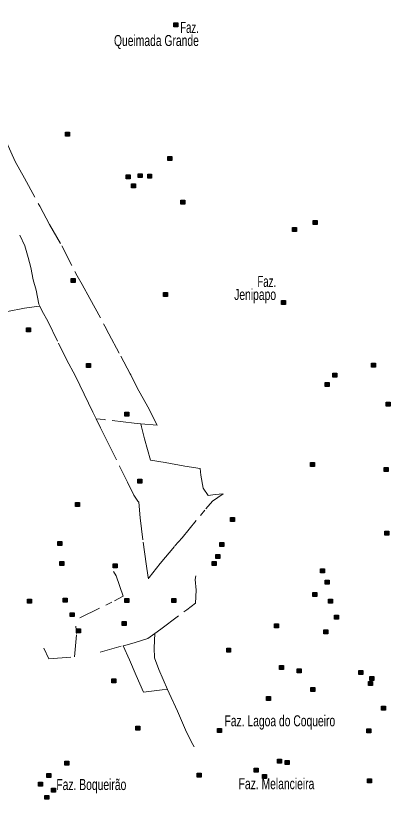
# Model space of a CAD drawing. Extents: x 445.6 to 500, y 8618.1 to 8673.4.
# Drawn here: x 452.48 to 457.92, y 8644.3 to 8655.7 of the extents above; entities that cross this region are included whole.
import ezdxf
from ezdxf.enums import TextEntityAlignment as Align

# ---------------------------------------------------------------- set-up
doc = ezdxf.new("R2010")
doc.units = 0
doc.header["$LTSCALE"] = 0.064
doc.linetypes.add('DOT_DASHED', pattern=[7.7, 5, -1.2, 0.3, -1.2])
doc.layers.add('2', color=7, linetype='Continuous', lineweight=25)
doc.layers.add('22', color=7, linetype='DOT_DASHED', lineweight=13)
doc.layers.add('61', color=7, linetype='Continuous')

msp = doc.modelspace()

# ---------------------------------------------------------------- hatches: boundary and pattern name
at = {"layer": '2'}
for points in [[(454.7723, 8655.5913), (454.8303, 8655.5913), (454.8303, 8655.5333), (454.7723, 8655.5333)], [(453.2027, 8654.0044), (453.2607, 8654.0044), (453.2607, 8653.9464), (453.2027, 8653.9464)], [(454.688, 8653.6496), (454.746, 8653.6496), (454.746, 8653.5916), (454.688, 8653.5916)], [(454.08, 8653.3819), (454.138, 8653.3819), (454.138, 8653.3239), (454.08, 8653.3239)], [(454.2557, 8653.3988), (454.3137, 8653.3988), (454.3137, 8653.3408), (454.2557, 8653.3408)], [(454.3941, 8653.3921), (454.4521, 8653.3921), (454.4521, 8653.3341), (454.3941, 8653.3341)], [(454.1577, 8653.2532), (454.2157, 8653.2532), (454.2157, 8653.1952), (454.1577, 8653.1952)], [(454.8772, 8653.0126), (454.9352, 8653.0126), (454.9352, 8652.9546), (454.8772, 8652.9546)], [(456.7994, 8652.718), (456.8574, 8652.718), (456.8574, 8652.66), (456.7994, 8652.66)], [(456.4988, 8652.6164), (456.5568, 8652.6164), (456.5568, 8652.5584), (456.4988, 8652.5584)], [(453.2852, 8651.8742), (453.3432, 8651.8742), (453.3432, 8651.8162), (453.2852, 8651.8162)], [(454.6219, 8651.671), (454.6799, 8651.671), (454.6799, 8651.613), (454.6219, 8651.613)], [(456.338, 8651.5524), (456.396, 8651.5524), (456.396, 8651.4944), (456.338, 8651.4944)], [(452.634, 8651.1585), (452.692, 8651.1585), (452.692, 8651.1005), (452.634, 8651.1005)], [(453.5082, 8650.6375), (453.5662, 8650.6375), (453.5662, 8650.5795), (453.5082, 8650.5795)], [(457.6418, 8650.6444), (457.6998, 8650.6444), (457.6998, 8650.5864), (457.6418, 8650.5864)], [(457.0816, 8650.4982), (457.1396, 8650.4982), (457.1396, 8650.4402), (457.0816, 8650.4402)], [(456.9696, 8650.3598), (457.0276, 8650.3598), (457.0276, 8650.3018), (456.9696, 8650.3018)], [(457.859, 8650.0749), (457.917, 8650.0749), (457.917, 8650.0169), (457.859, 8650.0169)], [(454.0636, 8649.9323), (454.1216, 8649.9323), (454.1216, 8649.8743), (454.0636, 8649.8743)], [(456.7603, 8649.1973), (456.8183, 8649.1973), (456.8183, 8649.1393), (456.7603, 8649.1393)], [(457.8286, 8649.1263), (457.8866, 8649.1263), (457.8866, 8649.0683), (457.8286, 8649.0683)], [(454.2494, 8648.9565), (454.3074, 8648.9565), (454.3074, 8648.8985), (454.2494, 8648.8985)], [(453.3441, 8648.6177), (453.4021, 8648.6177), (453.4021, 8648.5597), (453.3441, 8648.5597)], [(455.595, 8648.4011), (455.653, 8648.4011), (455.653, 8648.3431), (455.595, 8648.3431)], [(457.8387, 8648.2008), (457.8967, 8648.2008), (457.8967, 8648.1428), (457.8387, 8648.1428)], [(453.0908, 8648.0485), (453.1488, 8648.0485), (453.1488, 8647.9905), (453.0908, 8647.9905)], [(455.4431, 8648.035), (455.5011, 8648.035), (455.5011, 8647.977), (455.4431, 8647.977)], [(455.3823, 8647.8588), (455.4403, 8647.8588), (455.4403, 8647.8008), (455.3823, 8647.8008)], [(453.1172, 8647.7571), (453.1752, 8647.7571), (453.1752, 8647.6991), (453.1172, 8647.6991)], [(455.3317, 8647.7571), (455.3897, 8647.7571), (455.3897, 8647.6991), (455.3317, 8647.6991)], [(453.8947, 8647.7233), (453.9527, 8647.7233), (453.9527, 8647.6653), (453.8947, 8647.6653)], [(456.9017, 8647.6521), (456.9597, 8647.6521), (456.9597, 8647.5941), (456.9017, 8647.5941)], [(456.9726, 8647.4895), (457.0306, 8647.4895), (457.0306, 8647.4315), (456.9726, 8647.4315)], [(456.7902, 8647.3066), (456.8482, 8647.3066), (456.8482, 8647.2486), (456.7902, 8647.2486)], [(452.6494, 8647.2117), (452.7074, 8647.2117), (452.7074, 8647.1537), (452.6494, 8647.1537)], [(453.1662, 8647.2253), (453.2242, 8647.2253), (453.2242, 8647.1673), (453.1662, 8647.1673)], [(454.0602, 8647.2219), (454.1182, 8647.2219), (454.1182, 8647.1639), (454.0602, 8647.1639)], [(454.7459, 8647.2219), (454.8039, 8647.2219), (454.8039, 8647.1639), (454.7459, 8647.1639)], [(457.0179, 8647.2113), (457.0759, 8647.2113), (457.0759, 8647.1533), (457.0179, 8647.1533)], [(453.2709, 8647.0152), (453.3289, 8647.0152), (453.3289, 8646.9572), (453.2709, 8646.9572)], [(457.1091, 8646.9775), (457.1671, 8646.9775), (457.1671, 8646.9195), (457.1091, 8646.9195)], [(454.0218, 8646.8886), (454.0798, 8646.8886), (454.0798, 8646.8306), (454.0218, 8646.8306)], [(456.2369, 8646.8525), (456.2949, 8646.8525), (456.2949, 8646.7945), (456.2369, 8646.7945)], [(453.3621, 8646.7781), (453.4201, 8646.7781), (453.4201, 8646.7201), (453.3621, 8646.7201)], [(456.9523, 8646.7645), (457.0103, 8646.7645), (457.0103, 8646.7065), (456.9523, 8646.7065)], [(455.5411, 8646.4968), (455.5991, 8646.4968), (455.5991, 8646.4388), (455.5411, 8646.4388)], [(456.3065, 8646.2456), (456.3645, 8646.2456), (456.3645, 8646.1876), (456.3065, 8646.1876)], [(456.5666, 8646.1982), (456.6246, 8646.1982), (456.6246, 8646.1402), (456.5666, 8646.1402)], [(457.4604, 8646.1722), (457.5184, 8646.1722), (457.5184, 8646.1142), (457.4604, 8646.1142)], [(453.8726, 8646.0522), (453.9306, 8646.0522), (453.9306, 8645.9942), (453.8726, 8645.9942)], [(457.6192, 8646.0875), (457.6772, 8646.0875), (457.6772, 8646.0295), (457.6192, 8646.0295)], [(456.7625, 8645.9271), (456.8205, 8645.9271), (456.8205, 8645.8691), (456.7625, 8645.8691)], [(457.6023, 8646.013), (457.6603, 8646.013), (457.6603, 8645.955), (457.6023, 8645.955)], [(456.1173, 8645.7984), (456.1753, 8645.7984), (456.1753, 8645.7404), (456.1173, 8645.7404)], [(457.7903, 8645.6563), (457.8483, 8645.6563), (457.8483, 8645.5983), (457.7903, 8645.5983)], [(454.2234, 8645.3658), (454.2814, 8645.3658), (454.2814, 8645.3078), (454.2234, 8645.3078)], [(455.408, 8645.3308), (455.466, 8645.3308), (455.466, 8645.2728), (455.408, 8645.2728)], [(457.5775, 8645.3243), (457.6355, 8645.3243), (457.6355, 8645.2663), (457.5775, 8645.2663)], [(453.1921, 8644.8536), (453.2501, 8644.8536), (453.2501, 8644.7956), (453.1921, 8644.7956)], [(456.2795, 8644.8836), (456.3375, 8644.8836), (456.3375, 8644.8256), (456.2795, 8644.8256)], [(456.391, 8644.8633), (456.449, 8644.8633), (456.449, 8644.8053), (456.391, 8644.8053)], [(452.9294, 8644.677), (452.9874, 8644.677), (452.9874, 8644.619), (452.9294, 8644.619)], [(455.1108, 8644.6803), (455.1688, 8644.6803), (455.1688, 8644.6223), (455.1108, 8644.6223)], [(455.9422, 8644.755), (456.0002, 8644.755), (456.0002, 8644.697), (455.9422, 8644.697)], [(456.0599, 8644.66), (456.1179, 8644.66), (456.1179, 8644.602), (456.0599, 8644.602)], [(457.5876, 8644.5992), (457.6456, 8644.5992), (457.6456, 8644.5412), (457.5876, 8644.5412)], [(452.807, 8644.5487), (452.865, 8644.5487), (452.865, 8644.4907), (452.807, 8644.4907)], [(452.9962, 8644.464), (453.0542, 8644.464), (453.0542, 8644.406), (452.9962, 8644.406)], [(452.9016, 8644.359), (452.9596, 8644.359), (452.9596, 8644.301), (452.9016, 8644.301)]]:
    msp.add_hatch(color=256, dxfattribs=at).paths.add_polyline_path(points)

# ---------------------------------------------------------------- linework, layer by layer
for points in [[(454.7723, 8655.5913), (454.8303, 8655.5913), (454.8303, 8655.5333), (454.7723, 8655.5333)], [(453.2027, 8654.0044), (453.2607, 8654.0044), (453.2607, 8653.9464), (453.2027, 8653.9464)], [(454.688, 8653.6496), (454.746, 8653.6496), (454.746, 8653.5916), (454.688, 8653.5916)], [(454.08, 8653.3819), (454.138, 8653.3819), (454.138, 8653.3239), (454.08, 8653.3239)], [(454.2557, 8653.3988), (454.3137, 8653.3988), (454.3137, 8653.3408), (454.2557, 8653.3408)], [(454.3941, 8653.3921), (454.4521, 8653.3921), (454.4521, 8653.3341), (454.3941, 8653.3341)], [(454.1577, 8653.2532), (454.2157, 8653.2532), (454.2157, 8653.1952), (454.1577, 8653.1952)], [(454.8772, 8653.0126), (454.9352, 8653.0126), (454.9352, 8652.9546), (454.8772, 8652.9546)], [(456.7994, 8652.718), (456.8574, 8652.718), (456.8574, 8652.66), (456.7994, 8652.66)], [(456.4988, 8652.6164), (456.5568, 8652.6164), (456.5568, 8652.5584), (456.4988, 8652.5584)], [(453.2852, 8651.8742), (453.3432, 8651.8742), (453.3432, 8651.8162), (453.2852, 8651.8162)], [(454.6219, 8651.671), (454.6799, 8651.671), (454.6799, 8651.613), (454.6219, 8651.613)], [(456.338, 8651.5524), (456.396, 8651.5524), (456.396, 8651.4944), (456.338, 8651.4944)], [(452.634, 8651.1585), (452.692, 8651.1585), (452.692, 8651.1005), (452.634, 8651.1005)], [(453.5082, 8650.6375), (453.5662, 8650.6375), (453.5662, 8650.5795), (453.5082, 8650.5795)], [(457.6418, 8650.6444), (457.6998, 8650.6444), (457.6998, 8650.5864), (457.6418, 8650.5864)], [(457.0816, 8650.4982), (457.1396, 8650.4982), (457.1396, 8650.4402), (457.0816, 8650.4402)], [(456.9696, 8650.3598), (457.0276, 8650.3598), (457.0276, 8650.3018), (456.9696, 8650.3018)], [(457.859, 8650.0749), (457.917, 8650.0749), (457.917, 8650.0169), (457.859, 8650.0169)], [(454.0636, 8649.9323), (454.1216, 8649.9323), (454.1216, 8649.8743), (454.0636, 8649.8743)], [(456.7603, 8649.1973), (456.8183, 8649.1973), (456.8183, 8649.1393), (456.7603, 8649.1393)], [(457.8286, 8649.1263), (457.8866, 8649.1263), (457.8866, 8649.0683), (457.8286, 8649.0683)], [(454.2494, 8648.9565), (454.3074, 8648.9565), (454.3074, 8648.8985), (454.2494, 8648.8985)], [(453.3441, 8648.6177), (453.4021, 8648.6177), (453.4021, 8648.5597), (453.3441, 8648.5597)], [(455.595, 8648.4011), (455.653, 8648.4011), (455.653, 8648.3431), (455.595, 8648.3431)], [(457.8387, 8648.2008), (457.8967, 8648.2008), (457.8967, 8648.1428), (457.8387, 8648.1428)], [(453.0908, 8648.0485), (453.1488, 8648.0485), (453.1488, 8647.9905), (453.0908, 8647.9905)], [(455.4431, 8648.035), (455.5011, 8648.035), (455.5011, 8647.977), (455.4431, 8647.977)], [(455.3823, 8647.8588), (455.4403, 8647.8588), (455.4403, 8647.8008), (455.3823, 8647.8008)], [(453.1172, 8647.7571), (453.1752, 8647.7571), (453.1752, 8647.6991), (453.1172, 8647.6991)], [(455.3317, 8647.7571), (455.3897, 8647.7571), (455.3897, 8647.6991), (455.3317, 8647.6991)], [(453.8947, 8647.7233), (453.9527, 8647.7233), (453.9527, 8647.6653), (453.8947, 8647.6653)], [(456.9017, 8647.6521), (456.9597, 8647.6521), (456.9597, 8647.5941), (456.9017, 8647.5941)], [(456.9726, 8647.4895), (457.0306, 8647.4895), (457.0306, 8647.4315), (456.9726, 8647.4315)], [(456.7902, 8647.3066), (456.8482, 8647.3066), (456.8482, 8647.2486), (456.7902, 8647.2486)], [(452.6494, 8647.2117), (452.7074, 8647.2117), (452.7074, 8647.1537), (452.6494, 8647.1537)], [(453.1662, 8647.2253), (453.2242, 8647.2253), (453.2242, 8647.1673), (453.1662, 8647.1673)], [(454.0602, 8647.2219), (454.1182, 8647.2219), (454.1182, 8647.1639), (454.0602, 8647.1639)], [(454.7459, 8647.2219), (454.8039, 8647.2219), (454.8039, 8647.1639), (454.7459, 8647.1639)], [(457.0179, 8647.2113), (457.0759, 8647.2113), (457.0759, 8647.1533), (457.0179, 8647.1533)], [(453.2709, 8647.0152), (453.3289, 8647.0152), (453.3289, 8646.9572), (453.2709, 8646.9572)], [(457.1091, 8646.9775), (457.1671, 8646.9775), (457.1671, 8646.9195), (457.1091, 8646.9195)], [(454.0218, 8646.8886), (454.0798, 8646.8886), (454.0798, 8646.8306), (454.0218, 8646.8306)], [(456.2369, 8646.8525), (456.2949, 8646.8525), (456.2949, 8646.7945), (456.2369, 8646.7945)], [(453.3621, 8646.7781), (453.4201, 8646.7781), (453.4201, 8646.7201), (453.3621, 8646.7201)], [(456.9523, 8646.7645), (457.0103, 8646.7645), (457.0103, 8646.7065), (456.9523, 8646.7065)], [(455.5411, 8646.4968), (455.5991, 8646.4968), (455.5991, 8646.4388), (455.5411, 8646.4388)], [(456.3065, 8646.2456), (456.3645, 8646.2456), (456.3645, 8646.1876), (456.3065, 8646.1876)], [(456.5666, 8646.1982), (456.6246, 8646.1982), (456.6246, 8646.1402), (456.5666, 8646.1402)], [(457.4604, 8646.1722), (457.5184, 8646.1722), (457.5184, 8646.1142), (457.4604, 8646.1142)], [(453.8726, 8646.0522), (453.9306, 8646.0522), (453.9306, 8645.9942), (453.8726, 8645.9942)], [(457.6192, 8646.0875), (457.6772, 8646.0875), (457.6772, 8646.0295), (457.6192, 8646.0295)], [(456.7625, 8645.9271), (456.8205, 8645.9271), (456.8205, 8645.8691), (456.7625, 8645.8691)], [(457.6023, 8646.013), (457.6603, 8646.013), (457.6603, 8645.955), (457.6023, 8645.955)], [(456.1173, 8645.7984), (456.1753, 8645.7984), (456.1753, 8645.7404), (456.1173, 8645.7404)], [(457.7903, 8645.6563), (457.8483, 8645.6563), (457.8483, 8645.5983), (457.7903, 8645.5983)], [(454.2234, 8645.3658), (454.2814, 8645.3658), (454.2814, 8645.3078), (454.2234, 8645.3078)], [(455.408, 8645.3308), (455.466, 8645.3308), (455.466, 8645.2728), (455.408, 8645.2728)], [(457.5775, 8645.3243), (457.6355, 8645.3243), (457.6355, 8645.2663), (457.5775, 8645.2663)], [(453.1921, 8644.8536), (453.2501, 8644.8536), (453.2501, 8644.7956), (453.1921, 8644.7956)], [(456.2795, 8644.8836), (456.3375, 8644.8836), (456.3375, 8644.8256), (456.2795, 8644.8256)], [(456.391, 8644.8633), (456.449, 8644.8633), (456.449, 8644.8053), (456.391, 8644.8053)], [(452.9294, 8644.677), (452.9874, 8644.677), (452.9874, 8644.619), (452.9294, 8644.619)], [(455.1108, 8644.6803), (455.1688, 8644.6803), (455.1688, 8644.6223), (455.1108, 8644.6223)], [(455.9422, 8644.755), (456.0002, 8644.755), (456.0002, 8644.697), (455.9422, 8644.697)], [(456.0599, 8644.66), (456.1179, 8644.66), (456.1179, 8644.602), (456.0599, 8644.602)], [(457.5876, 8644.5992), (457.6456, 8644.5992), (457.6456, 8644.5412), (457.5876, 8644.5412)], [(452.807, 8644.5487), (452.865, 8644.5487), (452.865, 8644.4907), (452.807, 8644.4907)], [(452.9962, 8644.464), (453.0542, 8644.464), (453.0542, 8644.406), (452.9962, 8644.406)], [(452.9016, 8644.359), (452.9596, 8644.359), (452.9596, 8644.301), (452.9016, 8644.301)]]:
    msp.add_lwpolyline(points, close=True, dxfattribs=at)
at = {"layer": '22'}
msp.add_line((453.7021, 8646.4408), (454.0384, 8646.5343), dxfattribs=at)
for points in [[(452.2099, 8655.9575), (452.1588, 8655.5548), (452.0758, 8654.9816), (452.0325, 8654.676), (452.0073, 8654.557), (452.1047, 8654.3551), (452.278, 8653.991), (452.3429, 8653.8576), (452.4698, 8653.5773), (452.6034, 8653.3358), (452.8271, 8652.9248), (452.9685, 8652.6596), (453.1454, 8652.3495), (453.3699, 8651.9145), (453.4421, 8651.7884), (453.554, 8651.5829), (453.7741, 8651.1791), (453.8319, 8651.071), (454.0058, 8650.7444), (454.1393, 8650.4885), (454.1475, 8650.4728)], [(452.5378, 8652.5034), (452.6099, 8652.3501), (452.659, 8652.1784), (452.6959, 8652.0344), (452.7327, 8651.8535), (452.7756, 8651.7034), (452.8156, 8651.5015), (452.8288, 8651.4716)], [(452.0593, 8651.3592), (452.3585, 8651.3968), (452.6077, 8651.4433), (452.7802, 8651.4679), (452.8288, 8651.4716)], [(452.8288, 8651.4716), (452.8616, 8651.3973), (452.9445, 8651.2533), (453.0979, 8650.9345), (453.2145, 8650.6985), (453.3439, 8650.4546), (453.4697, 8650.1941), (453.596, 8649.9312), (453.6448, 8649.8338)], [(454.1475, 8650.4728), (454.244, 8650.2866), (454.3962, 8650.0067), (454.5333, 8649.7399), (454.2942, 8649.7605)], [(454.2942, 8649.7605), (454.1976, 8649.7688), (453.7645, 8649.8229), (453.6448, 8649.8338)], [(453.6448, 8649.8338), (453.7095, 8649.7044), (453.7985, 8649.5267), (453.9857, 8649.1466), (454.103, 8648.9118), (454.192, 8648.7218), (454.2534, 8648.639), (454.2657, 8648.6237), (454.2872, 8648.3939), (454.3304, 8648.0397), (454.3734, 8647.724), (454.4015, 8647.5281), (454.4049, 8647.5062), (454.4146, 8647.5243), (454.5758, 8647.7313), (454.7906, 8647.9857), (454.895, 8648.1053), (455.2398, 8648.5273), (455.3349, 8648.6376), (455.4914, 8648.7449), (455.3717, 8648.7326), (455.2735, 8648.7173), (455.1999, 8648.8276), (455.1662, 8649.0166), (455.157, 8649.1116), (454.936, 8649.1453), (454.6476, 8649.2005), (454.4358, 8649.2342), (454.3468, 8649.5438), (454.3031, 8649.7173), (454.2942, 8649.7605)], [(453.4077, 8646.9403), (453.9107, 8647.1855), (454.0375, 8647.2568), (453.9345, 8647.5496), (453.8995, 8647.6145)], [(454.4984, 8646.7124), (454.5848, 8646.7767), (454.9613, 8647.0578), (455.0881, 8647.1527), (455.096, 8647.3427), (455.0852, 8647.4958), (455.0931, 8647.5514)], [(452.8865, 8646.4991), (452.9582, 8646.3426), (453.3298, 8646.3739), (453.3611, 8646.7137), (453.3522, 8646.8166)], [(454.0384, 8646.5343), (454.042, 8646.5353), (454.1965, 8646.5788), (454.3986, 8646.6382), (454.4984, 8646.7124)], [(454.4984, 8646.7124), (454.4903, 8646.5028), (454.4943, 8646.3564), (454.5577, 8646.1902), (454.6815, 8645.8993)], [(454.0384, 8646.5343), (454.1295, 8646.3285), (454.2286, 8646.1029), (454.3356, 8645.8614), (454.605, 8645.8931), (454.6815, 8645.8993)], [(454.6815, 8645.8993), (454.7043, 8645.8458), (454.8271, 8645.5846), (454.9426, 8645.3126), (455.0298, 8645.1345), (455.0696, 8645.0658)]]:
    msp.add_lwpolyline(points, dxfattribs=at)

# ---------------------------------------------------------------- texts
at = {"layer": '61'}
for s, width, p in [('Faz.', 0.65, (455.1373, 8655.445)), ('Queimada Grande', 0.7, (455.1373, 8655.255)), ('Faz.', 0.65, (456.2584, 8651.7518)), ('Jenipapo', 0.7, (456.2584, 8651.5618))]:
    msp.add_text(s, height=0.16, dxfattribs=dict(at, width=width)).set_placement(p, align=Align.RIGHT)
at = {"layer": '61', "width": 0.7}
for s, p in [('Faz. Lagoa do Coqueiro', (455.5097, 8645.3628)), ('Faz. Boqueirão', (453.0682, 8644.4361))]:
    msp.add_text(s, height=0.16, dxfattribs=at).set_placement(p)
msp.add_text('Faz. Melancieira', height=0.16, dxfattribs=at).set_placement((456.2643, 8644.4486), align=Align.CENTER)

doc.saveas('drawing.dxf')
